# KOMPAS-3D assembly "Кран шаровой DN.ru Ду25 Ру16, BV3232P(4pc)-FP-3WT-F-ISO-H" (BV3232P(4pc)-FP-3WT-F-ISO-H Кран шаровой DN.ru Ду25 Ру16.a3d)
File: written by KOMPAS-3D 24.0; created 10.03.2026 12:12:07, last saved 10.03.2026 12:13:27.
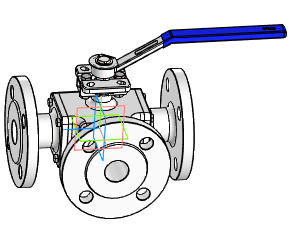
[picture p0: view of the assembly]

Document properties: Автор: R2D2; Полное имя файла: E:\Работа\Зайцев\BV3232P(4pc)-FP-3WT-F-ISO-H Кран шаровой DN.ru Ду15-100 Ру16\DN25\исходные материалы\BV3232P(4pc)-FP-3WT-F-ISO-H Кран шаровой DN.ru Ду25 Ру16.a3d

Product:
- Component [assembly]: Сборка1  | qty 1  | pos. 1  | Масса: 6.6873; Автор: R2D2; source file: dn25_3d_step.a3d
- Part/product: Кран шаровой DN.ru Ду25 Ру16  | designation BV3232P(4pc)-FP-3WT-F-ISO-H
    Масса: 5.6
    Раздел спецификации: Прочие изделия
    Примечание: D160-36348

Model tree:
1. Эскиз:1  (labels: Грань.Твердое тело1; Ребро.Твердое тело1)
2. Элемент выдавливания:1  (labels: Грань.Твердое тело1; Твердое тело1)
     Расстояние 2 = 0.01

Referenced files in E:\Работа\Зайцев\BV3232P(4pc)-FP-3WT-F-ISO-H Кран шаровой DN.ru Ду15-100 Ру16\DN25\исходные материалы\: dn25_3d_step.a3d
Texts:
  BV3232P(4pc)-FP-3WT-F-ISO-H
  Сборка1 Сборка1
  Ось Z.Начало координат
  Ось Y.Начало координат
